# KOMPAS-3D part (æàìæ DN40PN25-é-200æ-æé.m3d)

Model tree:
1. Объединить компоненты:1  (labels: СЕНС DN40PN25-В-200С)
2. Эскиз:1
3. Операция выдавливания:1
     Расстояние 1 = 14
4. Фаска:1
     Угол = 45; Длина 1 = 2; Длина 2 = 2

Referenced files in D:\Савин\!СЕНСОР\3D для заказчика\!Новый перечень\СЕНС\4. СЕНС-В-200С\DN40\: СЕНС DN40PN25-В-200С.a3d
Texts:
  СЕНС DN40PN25-В-200С-СВ
  ООО НПП Сенсор
  СЕНС DN40PN25-В-200С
